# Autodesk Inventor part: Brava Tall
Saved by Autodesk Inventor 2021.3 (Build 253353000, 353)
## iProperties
Created: 2022-09
Part Number: Brava Tall
Material: Generic
Document SubType Name: Modeling
Designer: Administrator
Density: 1 g/cm^3
Appearance: Default
Title: Brava Tall
Author: Administrator
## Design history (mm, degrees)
feature "Body1"
body "Solid1"
